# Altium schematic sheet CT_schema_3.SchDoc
size 365 x 192 mm
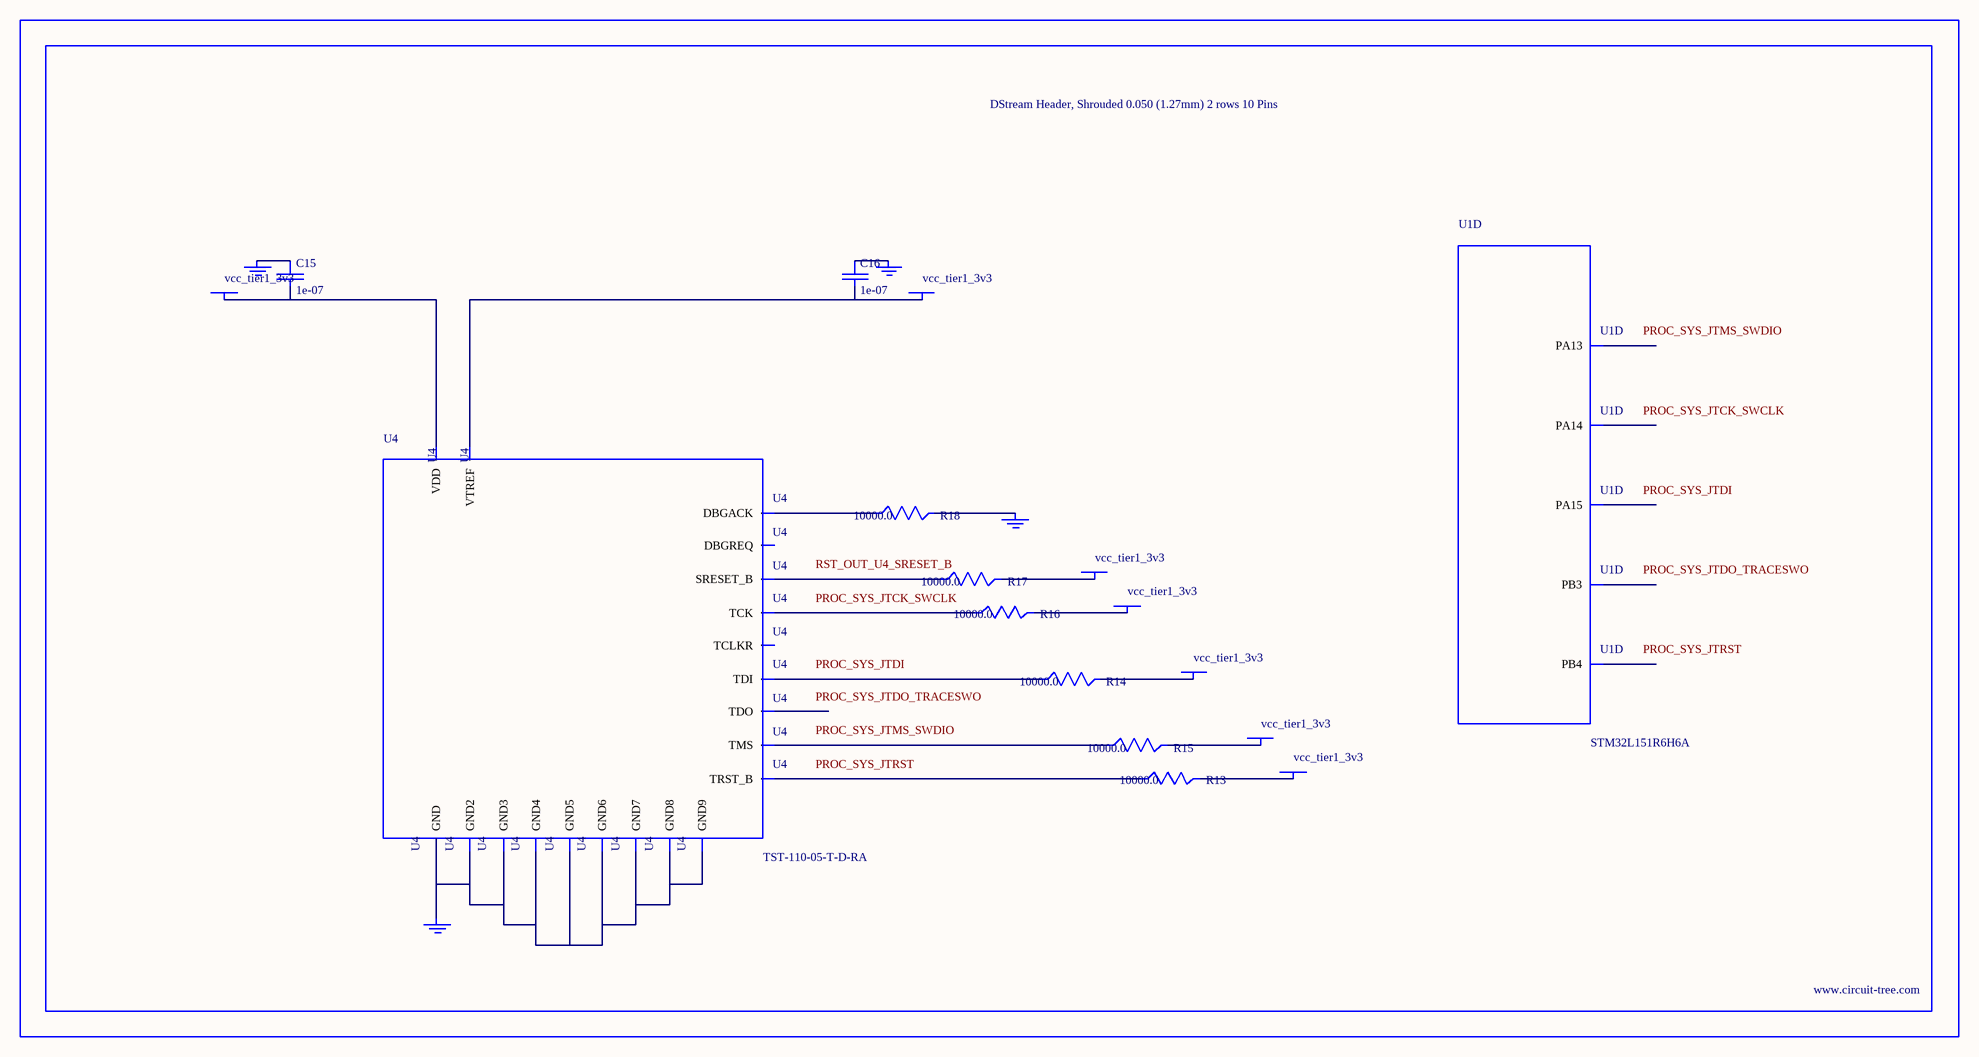
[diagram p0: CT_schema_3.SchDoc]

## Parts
BORDER2  (no value)
C15  1e-07  [C0402]
C16  1e-07  [C0402]
GND_INSTANCE_2_0  (no value)
GND_INSTANCE_2_1  (no value)
GND_INSTANCE_2_2  (no value)
GND_INSTANCE_2_3  (no value)
POWER_INSTANCE_2_0  vcc_tier1_3v3
POWER_INSTANCE_2_1  vcc_tier1_3v3
POWER_INSTANCE_2_2  vcc_tier1_3v3
POWER_INSTANCE_2_3  vcc_tier1_3v3
POWER_INSTANCE_2_4  vcc_tier1_3v3
POWER_INSTANCE_2_5  vcc_tier1_3v3
POWER_INSTANCE_2_6  vcc_tier1_3v3
R13  10000.0  [R0603]
R14  10000.0  [R0603]
R15  10000.0  [R0603]
R16  10000.0  [R0603]
R17  10000.0  [R0603]
R18  10000.0  [R0603]
U1  STM32L151R6H6A  [TFBGA64]  (part D of 7)
U4  TST-110-05-T-D-RA  [TST-110-05-T-D-RA]

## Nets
NetC15_1: C15.1 GND_INSTANCE_2_1.0(GND)
NetC15_2: C15.2 POWER_INSTANCE_2_1.0(PWR) U4.2(VDD)
NetC16_1: C16.1 GND_INSTANCE_2_0.0(GND)
NetC16_2: C16.2 POWER_INSTANCE_2_0.0(PWR) U4.1(VTREF)
NetGND_INSTANCE_2_2_0: GND_INSTANCE_2_2.0(GND) R18.2
NetGND_INSTANCE_2_3_0: GND_INSTANCE_2_3.0(GND) U4.4(GND) U4.6(GND2) U4.8(GND3) U4.10(GND4) U4.12(GND5) U4.14(GND6) U4.16(GND7) U4.18(GND8) U4.20(GND9)
NetPOWER_INSTANCE_2_2_0: POWER_INSTANCE_2_2.0(PWR) R13.2
NetPOWER_INSTANCE_2_3_0: POWER_INSTANCE_2_3.0(PWR) R14.2
NetPOWER_INSTANCE_2_4_0: POWER_INSTANCE_2_4.0(PWR) R15.2
NetPOWER_INSTANCE_2_5_0: POWER_INSTANCE_2_5.0(PWR) R16.2
NetPOWER_INSTANCE_2_6_0: POWER_INSTANCE_2_6.0(PWR) R17.2
NetR13_1: R13.1 U4.3(TRST_B)
NetR14_1: R14.1 U4.5(TDI)
NetR15_1: R15.1 U4.7(TMS)
NetR16_1: R16.1 U4.9(TCK)
NetR17_1: R17.1 U4.15(SRESET_B)
NetR18_1: R18.1 U4.19(DBGACK)

Not connected (* = marked no-connect by the designer): U1 A4(PB4) A5(PB3) A6(PA15) A7(PA14) A8(PA13); U4 11(TCLKR) 13(TDO) 17(DBGREQ)

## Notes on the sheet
- Labels drawn without touching a wire or pin: PROC_SYS_JTCK_SWCLK, PROC_SYS_JTDI, PROC_SYS_JTDO_TRACESWO, PROC_SYS_JTMS_SWDIO, PROC_SYS_JTRST, RST_OUT_U4_SRESET_B

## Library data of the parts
BORDER2 = BORDER_PAGE2
C15 C16 = C0402C104K3RACTU
GND_INSTANCE_2_0-GND_INSTANCE_2_3 = GND
POWER_INSTANCE_2_0-POWER_INSTANCE_2_6 = PWR
R13-R18 = RC0603JR-0710KL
